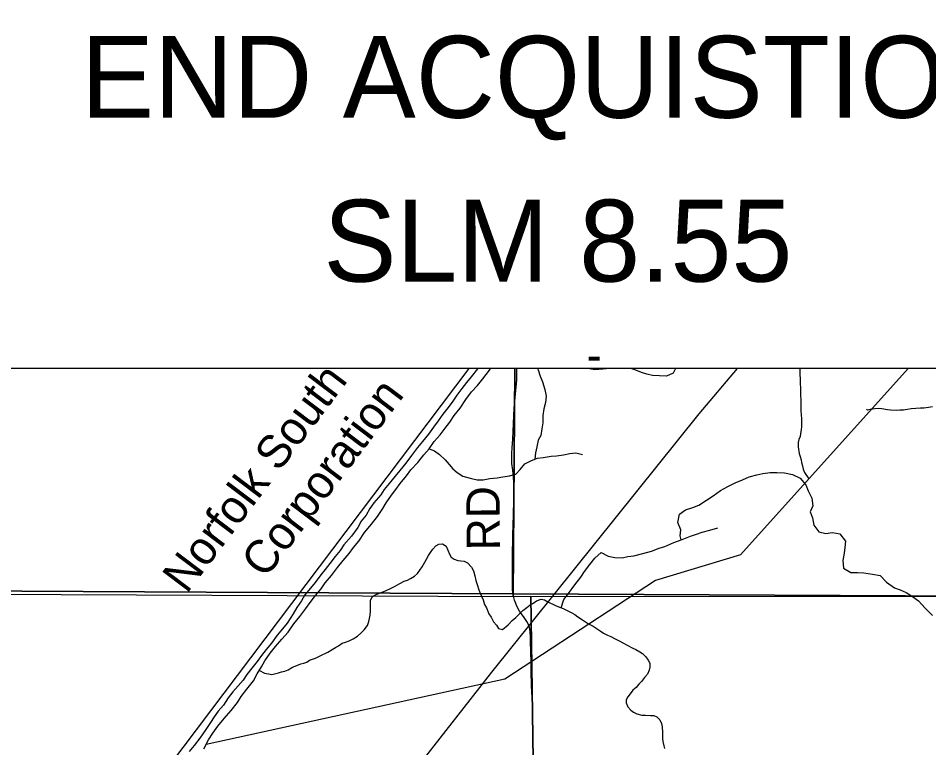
# Model space of a CAD drawing. Extents: x 0 to 34, y 0 to 22.
# Drawn here: x 5.951 to 7.507, y 15.614 to 16.861 of the extents above; entities that cross this region are included whole.
import ezdxf

# ---------------------------------------------------------------- set-up
doc = ezdxf.new("R2010")
doc.units = 0
for name, color, linetype in [('GM_X_Major_River', 7, 'Continuous'), ('GM_X_Minor_River', 7, 'Continuous'), ('GM_X_Rail_Line', 7, 'Continuous'), ('GM_X_Rail_Line_Text', 7, 'Continuous'), ('GM_X_Section', 7, 'Continuous'), ('GM_X_State_Route', 7, 'Continuous'), ('GM_X_Township_Road', 7, 'Continuous'), ('GM_X_Township_Road_Text', 7, 'Continuous'), ('SH_Text', 7, 'Continuous')]:
    doc.layers.add(name, color=color, linetype=linetype)

msp = doc.modelspace()

# ---------------------------------------------------------------- linework, layer by layer
at = {"layer": 'GM_X_Major_River'}
for points in [[(6.7364, 16.2626), (6.7361, 16.2622), (6.7249, 16.2485), (6.717, 16.239), (6.7091, 16.2283), (6.7008, 16.2169), (6.6937, 16.207), (6.6861, 16.1963), (6.6767, 16.1845), (6.6685, 16.1735), (6.6606, 16.1624), (6.6523, 16.1506), (6.6422, 16.1381), (6.6335, 16.1278), (6.6234, 16.1141), (6.6136, 16.1011), (6.6031, 16.0882), (6.5952, 16.0786), (6.585, 16.0661), (6.5764, 16.0561), (6.5707, 16.0466), (6.5591, 16.0333), (6.5519, 16.0234), (6.5455, 16.012), (6.5373, 16.0017), (6.5313, 15.991), (6.5204, 15.9762), (6.5076, 15.9613), (6.5012, 15.9514), (6.4929, 15.9415), (6.4835, 15.9297), (6.4756, 15.9194), (6.4685, 15.9099), (6.4587, 15.8969), (6.4508, 15.8874), (6.441, 15.8756), (6.435, 15.8657), (6.4275, 15.8543), (6.4208, 15.8432), (6.411, 15.8273), (6.4027, 15.8177), (6.3937, 15.8067), (6.3839, 15.7934), (6.3749, 15.7827), (6.367, 15.7724), (6.3595, 15.7621), (6.3501, 15.7503), (6.3418, 15.7396), (6.3354, 15.7301), (6.3272, 15.7206), (6.3177, 15.7103), (6.3102, 15.6996), (6.302, 15.6875), (6.2929, 15.6768), (6.2862, 15.6673), (6.2798, 15.6577), (6.2715, 15.6459), (6.2614, 15.6311), (6.252, 15.6185), (6.243, 15.6082)], [(6.2683, 15.6125), (6.2765, 15.6281), (6.284, 15.6392), (6.2923, 15.6517), (6.3032, 15.6647), (6.3153, 15.678), (6.3258, 15.6921), (6.3322, 15.702), (6.3416, 15.7146), (6.3532, 15.7291), (6.3596, 15.7409), (6.3667, 15.7527), (6.3723, 15.7629), (6.3817, 15.7763), (6.3908, 15.7877), (6.4017, 15.8003), (6.4122, 15.8121), (6.422, 15.8262), (6.4321, 15.8387), (6.4427, 15.8525), (6.4498, 15.8627), (6.4592, 15.8749), (6.469, 15.8864), (6.4754, 15.8963), (6.4863, 15.9088), (6.4968, 15.9226), (6.5066, 15.9344), (6.5167, 15.9466), (6.5243, 15.9565), (6.5333, 15.9675), (6.543, 15.9824), (6.5547, 15.9968), (6.5649, 16.0098), (6.5742, 16.0235), (6.5799, 16.033), (6.5893, 16.0463), (6.5964, 16.0559), (6.6039, 16.0661), (6.6145, 16.0795), (6.622, 16.0894), (6.634, 16.1023), (6.6442, 16.1149), (6.6532, 16.1252), (6.6622, 16.1378), (6.6724, 16.1492), (6.6806, 16.161), (6.6885, 16.1709), (6.6961, 16.1823), (6.7062, 16.1949), (6.716, 16.2098), (6.7257, 16.2231), (6.7359, 16.2334), (6.7453, 16.2452), (6.7562, 16.2597), (6.7583, 16.2626)]]:
    msp.add_lwpolyline(points, dxfattribs=at)
at = {"layer": 'GM_X_Minor_River'}
for points in [[(7.4718, 16.2626), (7.1856, 15.9444), (7.0401, 15.9001), (6.7829, 15.7319), (6.2724, 15.6203)], [(6.8385, 16.2626), (6.8396, 16.2604), (6.8429, 16.2498), (6.8471, 16.2399), (6.8512, 16.2266), (6.8534, 16.2156), (6.8522, 16.2046), (6.8495, 16.1936), (6.8476, 16.1822), (6.8475, 16.1697), (6.846, 16.1594), (6.8441, 16.1484), (6.8395, 16.1401), (6.8372, 16.1287), (6.8349, 16.1185), (6.8337, 16.1079)], [(6.9641, 16.2626), (6.9613, 16.2625), (6.9504, 16.2617), (6.9367, 16.2607), (6.9237, 16.2626)], [(7.0742, 16.2626), (7.0702, 16.2547), (7.0592, 16.2498), (7.0471, 16.2499), (7.035, 16.2507), (7.0256, 16.253), (7.0161, 16.2557), (7.0067, 16.2596), (6.9978, 16.2626)], [(7.2865, 16.2626), (7.2867, 16.2607), (7.2867, 16.2523), (7.2871, 16.2451), (7.2871, 16.2367), (7.2878, 16.2295), (7.2879, 16.2169)], [(7.2879, 16.2169), (7.2883, 16.2093), (7.2883, 16.1957), (7.2887, 16.1896), (7.289, 16.1843), (7.2894, 16.1759), (7.2898, 16.1698), (7.2898, 16.1637), (7.2891, 16.1577), (7.288, 16.1516), (7.2872, 16.1466), (7.2853, 16.1413), (7.2842, 16.136), (7.2842, 16.1288), (7.2857, 16.1174), (7.2873, 16.1124), (7.2888, 16.1067), (7.2899, 16.1018), (7.2914, 16.0961), (7.2926, 16.0908), (7.2945, 16.0851), (7.302, 16.0739)], [(7.4009, 16.1934), (7.4023, 16.1921), (7.4072, 16.1932), (7.4151, 16.1943), (7.4219, 16.1947), (7.4269, 16.1943), (7.4367, 16.1924), (7.4416, 16.192), (7.4522, 16.1916), (7.4579, 16.192), (7.464, 16.1923), (7.4708, 16.1931), (7.4768, 16.1942), (7.4928, 16.1957), (7.4984, 16.1957), (7.5068, 16.1968), (7.5132, 16.1976)], [(6.6535, 16.1257), (6.6624, 16.122), (6.6711, 16.1155), (6.6809, 16.1067), (6.6873, 16.0987), (6.6941, 16.0915), (6.7013, 16.085), (6.7111, 16.0789), (6.7232, 16.0754), (6.7352, 16.0727), (6.7458, 16.0726), (6.7572, 16.0745), (6.7693, 16.0756), (6.7791, 16.0778), (6.7905, 16.0793), (6.8014, 16.0819), (6.8087, 16.0902), (6.817, 16.1), (6.828, 16.1053), (6.8386, 16.1094), (6.8484, 16.1108), (6.8617, 16.1127), (6.8711, 16.1134), (6.8829, 16.1149), (6.8938, 16.1175), (6.9041, 16.1185), (6.9154, 16.1155)], [(7.0839, 15.9699), (7.0825, 15.977), (7.0836, 15.9868), (7.0783, 15.9993), (7.0812, 16.0138), (7.0914, 16.021), (7.1039, 16.0249), (7.1144, 16.0291), (7.1272, 16.0375), (7.1389, 16.0452), (7.1514, 16.054), (7.1638, 16.0608), (7.1763, 16.0674), (7.1887, 16.0727), (7.2001, 16.0773), (7.2133, 16.0812), (7.2235, 16.0835), (7.236, 16.0847), (7.2473, 16.0852), (7.2606, 16.0845), (7.2742, 16.0815), (7.2875, 16.0751), (7.297, 16.0638), (7.3008, 16.0539), (7.3073, 16.041), (7.3089, 16.0281), (7.3044, 16.0175), (7.3086, 16.0073), (7.3105, 15.9947), (7.3193, 15.9838), (7.331, 15.9808), (7.3428, 15.9824), (7.3553, 15.9802), (7.3648, 15.9677), (7.3637, 15.9567), (7.3626, 15.9472), (7.3604, 15.9346), (7.3616, 15.9217), (7.3737, 15.9142), (7.3855, 15.9143), (7.3964, 15.9132), (7.4112, 15.9113), (7.4241, 15.9091), (7.4351, 15.8978), (7.4488, 15.8876), (7.4582, 15.8846), (7.4685, 15.8801), (7.4791, 15.8733), (7.4897, 15.8654), (7.5011, 15.8533), (7.5133, 15.8405)], [(6.8791, 15.8537), (6.8837, 15.8678), (6.8916, 15.8781), (6.9025, 15.893), (6.9126, 15.9059), (6.9186, 15.9155), (6.9277, 15.9276), (6.9363, 15.9383), (6.9472, 15.9482), (6.959, 15.9422), (6.9707, 15.9396), (6.9832, 15.9393), (6.993, 15.9412), (7.0029, 15.9424), (7.0187, 15.9463), (7.0331, 15.9505), (7.0463, 15.9555), (7.0561, 15.9586), (7.0716, 15.9651), (7.0856, 15.9705), (7.0999, 15.9759), (7.1101, 15.9794), (7.1199, 15.9828), (7.1332, 15.9863), (7.1468, 15.9905)], [(6.3632, 15.7468), (6.3718, 15.7419), (6.3787, 15.7407), (6.3843, 15.7399), (6.3893, 15.7407), (6.3961, 15.7426), (6.401, 15.7445), (6.4067, 15.7456), (6.4127, 15.7479), (6.4199, 15.752), (6.4275, 15.7551), (6.4339, 15.7577), (6.4392, 15.7589), (6.4441, 15.7607), (6.449, 15.7642), (6.4593, 15.7679), (6.468, 15.7721), (6.4805, 15.7778), (6.4876, 15.7823), (6.4933, 15.7858), (6.4982, 15.7888), (6.505, 15.793), (6.5103, 15.7952), (6.5164, 15.7975), (6.5236, 15.8009), (6.5308, 15.8055), (6.5368, 15.8104), (6.5425, 15.8161), (6.5478, 15.8233), (6.5501, 15.8305), (6.5516, 15.8354), (6.5527, 15.8411), (6.5534, 15.8484), (6.5534, 15.8662), (6.556, 15.8727), (6.5613, 15.8757), (6.57, 15.8795), (6.5799, 15.8833), (6.5871, 15.8867), (6.5954, 15.8909), (6.6033, 15.8954), (6.6105, 15.8992), (6.6162, 15.9011), (6.6215, 15.9037), (6.6283, 15.9079), (6.6332, 15.9125), (6.6374, 15.9178), (6.6416, 15.9238), (6.6457, 15.9318), (6.6487, 15.9371), (6.6521, 15.9432), (6.6555, 15.9485), (6.6597, 15.9538), (6.6646, 15.9595), (6.6699, 15.9622), (6.6763, 15.9633), (6.6824, 15.9591), (6.6854, 15.9523), (6.6881, 15.9454), (6.6908, 15.9405), (6.6961, 15.9371), (6.7025, 15.9348), (6.7074, 15.934), (6.7131, 15.9332), (6.7188, 15.9306), (6.7256, 15.9233), (6.729, 15.9169), (6.7313, 15.9085), (6.7332, 15.9005), (6.7359, 15.8918), (6.7374, 15.8861), (6.7397, 15.8796), (6.7431, 15.8724), (6.7458, 15.8671), (6.748, 15.8591), (6.7511, 15.8534), (6.7556, 15.8435), (6.7591, 15.8378), (6.7636, 15.8298), (6.7682, 15.8241), (6.7716, 15.8184), (6.7788, 15.8168), (6.7886, 15.8244), (6.7954, 15.832), (6.8015, 15.8373), (6.8071, 15.843), (6.8136, 15.8491), (6.8204, 15.8544), (6.8257, 15.8589), (6.8306, 15.8612), (6.837, 15.8658), (6.845, 15.8684), (6.8507, 15.8673), (6.8563, 15.8642), (6.8692, 15.8577), (6.876, 15.8547), (6.8821, 15.8528), (6.887, 15.8501), (6.8969, 15.8452)], [(6.8969, 15.8452), (6.9022, 15.8421), (6.9075, 15.8383), (6.9154, 15.8333), (6.9208, 15.8299), (6.9257, 15.8265), (6.9336, 15.8223), (6.9389, 15.8189), (6.9458, 15.8143), (6.9511, 15.8105), (6.9579, 15.8071), (6.964, 15.8044), (6.9712, 15.8009), (6.978, 15.7975), (6.9856, 15.7933), (6.9916, 15.7899), (7, 15.7853), (7.0064, 15.7823), (7.0132, 15.7785), (7.0182, 15.7754), (7.0238, 15.7697), (7.0276, 15.7644), (7.0303, 15.7591), (7.0307, 15.7522), (7.0295, 15.7473), (7.0265, 15.7404), (7.0216, 15.7347), (7.0163, 15.7275), (7.0114, 15.7234), (7.0073, 15.7177), (7.0016, 15.7127), (6.997, 15.7067), (6.9929, 15.7013), (6.9902, 15.6964), (6.9899, 15.6911), (6.9929, 15.6842), (6.9978, 15.6785), (7.0028, 15.6751), (7.0081, 15.6724), (7.0168, 15.6705), (7.0232, 15.6701), (7.0316, 15.6697), (7.0372, 15.6694), (7.0425, 15.6671), (7.0475, 15.6621), (7.0505, 15.656), (7.0513, 15.6503), (7.052, 15.6408), (7.0521, 15.6302), (7.0528, 15.6252), (7.0544, 15.618), (7.0555, 15.6131)]]:
    msp.add_lwpolyline(points, dxfattribs=at)
at = {"layer": 'GM_X_Rail_Line'}
for points in [[(5.0891, 14.1), (5.1221, 14.1437), (5.272, 14.3429), (5.3972, 14.5075), (5.4919, 14.6329), (5.5336, 14.6891), (5.7438, 14.9674), (6.7216, 16.2626)], [(6.3861, 14.1), (6.3755, 14.1148), (6.3611, 14.1404), (6.3547, 14.1709), (6.3313, 14.8083), (6.3219, 15.0535), (6.3265, 15.1211), (6.3378, 15.1698), (6.3598, 15.2213), (6.4214, 15.3109), (6.7603, 15.7438), (7.1147, 16.1854), (7.1801, 16.2626)]]:
    msp.add_lwpolyline(points, dxfattribs=at)
at = {"layer": 'GM_X_Section'}
for points in [[(5.7774, 16.8294), (5.644, 16.8278), (5.6379, 15.8781), (6.7969, 15.8732), (6.8, 16.2626), (5.7774, 16.2626)], [(6.8, 16.2626), (6.7969, 15.8732), (6.8272, 15.8734), (7.8036, 15.873), (7.8054, 16.2626)], [(6.8272, 15.8734), (6.8411, 14.8726), (5.6415, 14.8783), (5.6379, 15.8781), (6.7969, 15.8732)], [(6.8272, 15.8734), (7.8036, 15.873), (7.8312, 15.8725), (7.8581, 14.855), (6.8411, 14.8726)]]:
    msp.add_lwpolyline(points, close=True, dxfattribs=at)
at = {"layer": 'GM_X_State_Route'}
msp.add_lwpolyline([(7.8042, 16.2626), (7.8024, 15.8725), (6.7968, 15.8774), (5.6416, 15.8841), (5.6436, 15.468), (5.6455, 14.1), (8.9, 14.1), (8.9, 18.8876), (8.7984, 18.8872), (8.8033, 17.8763), (8.296, 17.8766), (7.7904, 17.865), (7.8038, 16.9797), (7.9972, 16.9797), (7.9972, 16.2626)], close=True, dxfattribs=at)
msp.add_lwpolyline([(5.6474, 17.3472), (5.6423, 16.0151), (5.6416, 15.8841), (6.7968, 15.8774), (7.8024, 15.8725), (7.8042, 16.2626), (5.7774, 16.2626), (5.7774, 16.9797)], dxfattribs=at)
at = {"layer": 'GM_X_Township_Road'}
for points in [[(6.7972, 15.8759), (6.797, 15.8768), (6.7965, 15.8793), (6.7958, 15.8857), (6.7958, 15.8934), (6.7958, 15.9012), (6.7958, 15.9071), (6.7958, 15.9151), (6.7958, 15.94), (6.7965, 15.9775), (6.797, 15.9969), (6.7973, 16.011), (6.7981, 16.0396), (6.7981, 16.0582), (6.7981, 16.0698), (6.7965, 16.089), (6.7949, 16.1006), (6.7945, 16.1054), (6.7945, 16.1096), (6.7945, 16.1131), (6.7947, 16.1179), (6.7953, 16.1272), (6.7962, 16.142), (6.7988, 16.1947), (6.8027, 16.2371), (6.803, 16.2432), (6.8033, 16.2496), (6.8033, 16.2586), (6.8032, 16.2626)], [(6.8309, 15.6058), (6.8305, 15.6495), (6.8303, 15.6806), (6.8302, 15.6837), (6.8297, 15.6899), (6.8283, 15.7206), (6.828, 15.7286), (6.8278, 15.738), (6.8274, 15.751), (6.8274, 15.7584), (6.8272, 15.78), (6.8268, 15.7939), (6.8265, 15.8023), (6.8259, 15.814), (6.825, 15.8199), (6.8234, 15.8244), (6.8212, 15.8285), (6.8158, 15.8369), (6.808, 15.8477), (6.8039, 15.8553), (6.8002, 15.8639), (6.7994, 15.8669), (6.7982, 15.8711), (6.7972, 15.8759)]]:
    msp.add_lwpolyline(points, dxfattribs=at)
at = {"layer": 'SH_Text'}
msp.add_lwpolyline([(5.7774, 16.9797), (7.9972, 16.9797), (7.9972, 16.2626), (5.7774, 16.2626)], close=True, dxfattribs=at)

# ---------------------------------------------------------------- texts
at = {"layer": 'GM_X_Rail_Line_Text'}
for s, rotation, p in [('Norfolk South', 52.91, (6.239, 15.8763)), ('Corporation', 52.8739, (6.3735, 15.902))]:
    msp.add_text(s, height=0.056629, rotation=rotation, dxfattribs=at).set_placement(p)
at = {"layer": 'GM_X_Township_Road_Text'}
for s, height, rotation, p in [('-', 0.0568, 0.1594, (6.9228, 16.2575)), ('RD', 0.05682, 90.4814, (6.7745, 15.9521))]:
    msp.add_text(s, height=height, rotation=rotation, dxfattribs=at).set_placement(p)
at = {"layer": 'SH_Text'}
for s, p in [('END ACQUISTION', (6.0584, 16.6912)), ('SLM 8.55', (6.4727, 16.4112))]:
    msp.add_text(s, height=0.14, dxfattribs=at).set_placement(p)

doc.saveas('drawing.dxf')
